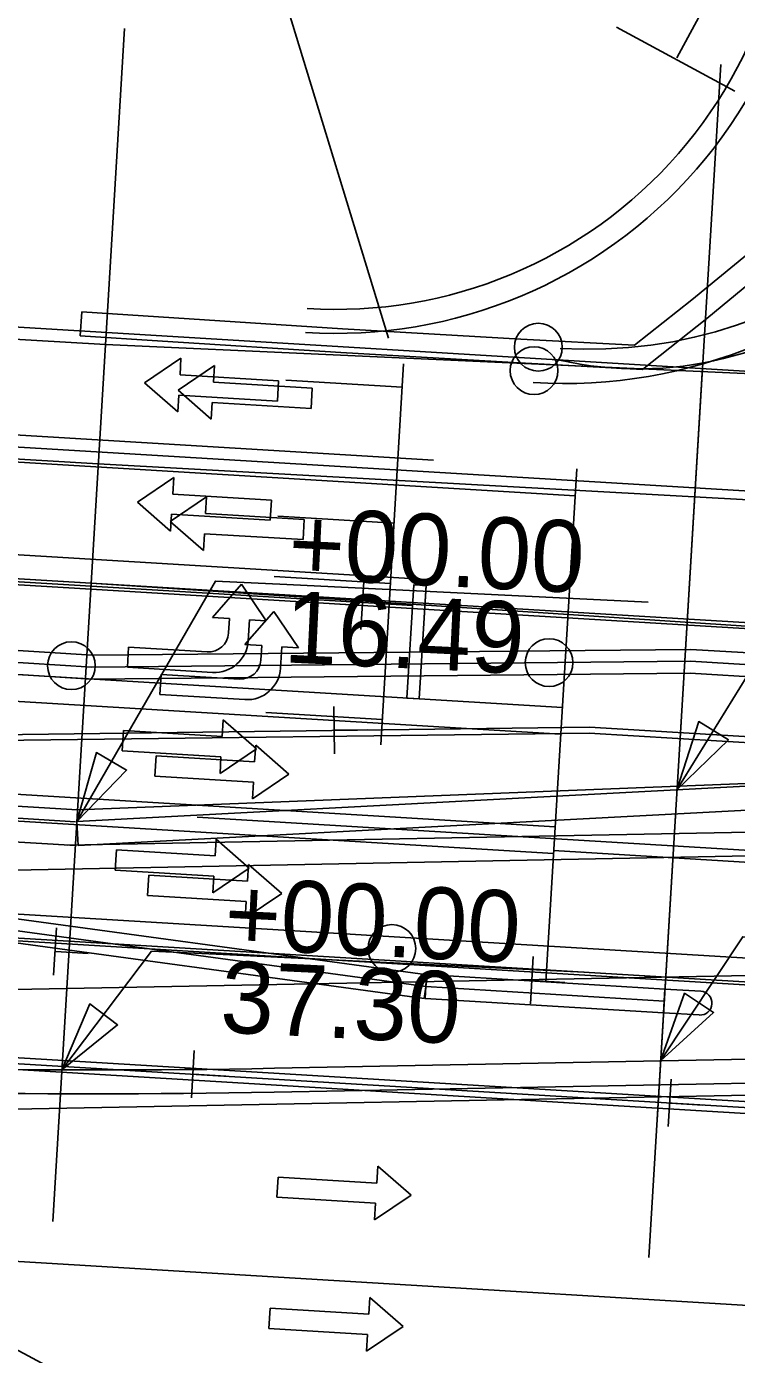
# Model space of a CAD drawing. Extents: x 659657 to 668193, y 633084 to 648639.
# Drawn here: x 662476.4 to 662535.8, y 642371.9 to 642483 of the extents above; entities that cross this region are included whole.
import ezdxf

# ---------------------------------------------------------------- set-up
doc = ezdxf.new("R2010")
doc.units = 0
for name, color, linetype in [('R_MOT_Stage 1', 7, 'Continuous'), ('R_MOT_Stage 1_Striping', 7, 'Continuous'), ('R_MOT_Stage 1A', 7, 'Continuous'), ('R_MOT_Stage 1A_Striping', 7, 'Continuous'), ('R_MOT_Stage 1B', 7, 'Continuous'), ('R_MOT_Stage 1B_Striping', 7, 'Continuous'), ('R_MOT_Stage 1C', 7, 'Continuous'), ('R_MOT_Stage 1C_Striping', 7, 'Continuous'), ('R_MOT_Stage 2', 7, 'Continuous'), ('R_MOT_Stage 2_Striping', 7, 'Continuous'), ('R_MOT_Stage 3', 7, 'Continuous'), ('R_MOT_Stage 3_Striping', 7, 'Continuous'), ('R_MOT_Stage 4', 7, 'Continuous'), ('R_MOT_STAGE 4_ALG', 7, 'Continuous'), ('R_MOT_Stage 4_Striping', 7, 'Continuous'), ('R_MOT_Stage 5', 7, 'Continuous'), ('R_MOT_Stage 5_Striping', 7, 'Continuous'), ('R_MOT_Stage 5_Striping_PPM', 7, 'Continuous'), ('R_ROW Annot', 7, 'Continuous'), ('T_SIGNAL CONTROL CABINET', 7, 'Continuous'), ('TEXT_TEMP_SIGNAL_POLES_STAGE 2', 7, 'Continuous')]:
    doc.layers.add(name, color=color, linetype=linetype)

msp = doc.modelspace()

# ---------------------------------------------------------------- linework, layer by layer
for p, q in [((662498.2, 642436.28), (662528.45, 642434.81)), ((662472.14, 642402.33), (662675.98, 642406.25)), ((662492.86, 642405.32), (662523.1, 642403.86))]:
    msp.add_line(p, q)
for points in [[(662530.86, 642419.1), (662541.99, 642437.12), (662547.99, 642436.83)], [(662480.61, 642416.45), (662492.21, 642436.57), (662498.2, 642436.28)], [(662529.49, 642396.43), (662536.36, 642406.81), (662542.36, 642406.52)], [(662479.35, 642395.67), (662486.87, 642405.62), (662492.86, 642405.32)]]:
    msp.add_lwpolyline(points)
for points in [[(662530.86, 642419.1), (662532.68, 642424.82), (662535.16, 642423.29)], [(662480.61, 642416.45), (662482.25, 642422.22), (662484.78, 642420.76)], [(662529.49, 642396.43), (662531.49, 642402.09), (662533.92, 642400.48)], [(662479.35, 642395.67), (662481.7, 642401.19), (662484.02, 642399.44)]]:
    msp.add_lwpolyline(points, close=True)
at = {"layer": 'R_MOT_Stage 1'}
for p, q in [((662478.67, 642403.6), (662478.91, 642407.57)), ((662478.84, 642405.57), (662481.55, 642405.41)), ((662518.59, 642401.19), (662518.83, 642405.16)), ((662518.77, 642403.16), (662521.48, 642403))]:
    msp.add_line(p, q, dxfattribs=at)
at = {"layer": 'R_MOT_Stage 1_Striping'}
for p, q in [((662367.61, 642453.06), (662522.33, 642443.72)), ((662367.01, 642443.08), (662508.75, 642434.52)), ((662421.3, 642429.78), (662521.12, 642423.76)), ((662365.8, 642423.12), (662520.52, 642413.78))]:
    msp.add_line(p, q, dxfattribs=at)
msp.add_lwpolyline([(662365.81, 642413.1), (662545.74, 642402.23), (662679.56, 642392.6)], dxfattribs=at)
at = {"layer": 'R_MOT_Stage 1A'}
msp.add_line((662480.9, 642457.09), (662481.03, 642459.09), dxfattribs=at)
for points in [[(662527.31, 642456.32), (662532.09, 642460.1), (662536.76, 642463.93), (662540.34, 642467.13), (662542.02, 642468.94), (662544, 642471.14), (662545.88, 642473.9), (662547.63, 642476.26), (662549.02, 642478.81), (662550.33, 642481.44), (662551.24, 642483.77), (662552.03, 642485.85), (662552.98, 642488.65), (662553.79, 642491.48), (662554.41, 642494.35), (662554.82, 642497.29), (662555.14, 642500.27), (662555.33, 642502.83), (662555.22, 642505.76), (662555.03, 642508.73), (662554.83, 642511.69), (662554.41, 642514.64), (662554.02, 642517.48)], [(662527.96, 642454.29), (662533.35, 642458.54), (662537.03, 642461.57), (662538.06, 642462.41), (662541.75, 642465.7), (662543.5, 642467.59), (662545.57, 642469.91), (662547.51, 642472.74), (662549.32, 642475.18), (662550.8, 642477.89), (662552.16, 642480.63), (662553.1, 642483.05)], [(662481.03, 642459.09), (662502.85, 642457.69), (662517.79, 642456.82), (662527.31, 642456.32)], [(662480.9, 642457.09), (662487.78, 642456.65), (662502.72, 642455.7), (662517.68, 642454.82), (662527.96, 642454.29)]]:
    msp.add_lwpolyline(points, dxfattribs=at)
at = {"layer": 'R_MOT_Stage 1A_Striping'}
for points in [[(662527.96, 642454.29), (662533.35, 642458.54), (662537.03, 642461.57), (662538.06, 642462.41), (662541.75, 642465.7), (662543.5, 642467.59), (662545.57, 642469.91), (662547.51, 642472.74), (662549.32, 642475.18), (662550.8, 642477.89), (662552.16, 642480.63), (662553.1, 642483.05)], [(662480.9, 642457.09), (662487.78, 642456.65), (662502.72, 642455.7), (662517.68, 642454.82), (662527.96, 642454.29)]]:
    msp.add_lwpolyline(points, dxfattribs=at)
at = {"layer": 'R_MOT_Stage 1B'}
msp.add_arc((662502.32, 642497.3), 38, 266.3389, 11.5452, dxfattribs=at)
at = {"layer": 'R_MOT_Stage 1B_Striping'}
msp.add_arc((662502.32, 642497.3), 40, 266.3389, 11.5452, dxfattribs=at)
at = {"layer": 'R_MOT_Stage 1C'}
msp.add_circle((662518.89, 642454.18), 2, dxfattribs=at)
at = {"layer": 'R_MOT_Stage 1C_Striping'}
msp.add_arc((662521.39, 642495.1), 42, 266.4975, 11.5452, dxfattribs=at)
at = {"layer": 'R_MOT_Stage 2'}
for p, q in [((662532.85, 642402.26), (662529.85, 642402.44)), ((662529.73, 642400.45), (662532.73, 642400.27))]:
    msp.add_line(p, q, dxfattribs=at)
for points in [[(662469.95, 642407.06), (662509.69, 642401.66), (662509.96, 642403.64), (662470.22, 642409.05)], [(662509.89, 642403.65), (662509.77, 642401.65), (662529.73, 642400.45), (662529.85, 642402.44)]]:
    msp.add_lwpolyline(points, close=True, dxfattribs=at)
for centre in [(662519.25, 642456.14), (662506.99, 642405.83)]:
    msp.add_circle(centre, 2, dxfattribs=at)
msp.add_arc((662532.79, 642401.26), 1, 266.5452, 86.5452, dxfattribs=at)
at = {"layer": 'R_MOT_Stage 2_Striping'}
for points in [[(662412.66, 642452.6), (662510.48, 642446.69)], [(662412.06, 642442.61), (662509.88, 642436.71)], [(662411.46, 642432.63), (662521.26, 642426)], [(662410.85, 642422.65), (662520.65, 642416.02)], [(662470.14, 642409.05), (662544.65, 642404.55)]]:
    msp.add_lwpolyline(points, dxfattribs=at)
msp.add_lwpolyline([(662509.28, 642426.73), (662509.87, 642436.21), (662508.84, 642436.27), (662508.25, 642426.79)], close=True, dxfattribs=at)
msp.add_arc((662527.6, 642484.6), 30.27, 257.4346, 2.4822, dxfattribs=at)
at = {"layer": 'R_MOT_Stage 3'}
for p, q in [((662301.8, 642441.26), (662481.9, 642430.38)), ((662345.58, 642436.61), (662481.85, 642428.38)), ((662481.9, 642430.38), (662532.02, 642430.86)), ((662532.02, 642430.86), (662660.67, 642423.1)), ((662481.85, 642428.38), (662531.97, 642428.86)), ((662531.97, 642428.86), (662661.25, 642421.06)), ((662497.17, 642395.81), (662624.87, 642398.26)), ((662497.13, 642393.81), (662624.91, 642396.26))]:
    msp.add_line(p, q, dxfattribs=at)
for centre in [(662520.15, 642429.75), (662480.16, 642429.49)]:
    msp.add_circle(centre, 2, dxfattribs=at)
for centre in [(662482.52, 643157.67), (662482.48, 643155.67)]:
    msp.add_arc(centre, 762, 266.54523, 271.10143, dxfattribs=at)
at = {"layer": 'R_MOT_Stage 3_Striping'}
for p, q in [((661885.4, 642492.44), (662483.02, 642456.36)), ((661899.48, 642481.57), (662482.41, 642446.38)), ((662012.67, 642464.72), (662481.81, 642436.4)), ((662483.02, 642456.36), (662582.93, 642451.83)), ((662482.41, 642446.38), (662582.26, 642440.85)), ((662481.81, 642436.4), (662581.6, 642429.87)), ((661979.29, 642409.63), (662536.82, 642375.97)), ((662471.94, 642392.32), (662695.17, 642396.61))]:
    msp.add_line(p, q, dxfattribs=at)
at = {"layer": 'R_MOT_Stage 4'}
for p, q in [((662480.49, 642416.44), (662024.68, 642443.96)), ((662480.49, 642414.44), (662024.34, 642441.98)), ((662479.84, 642414.48), (662675.81, 642418.25))]:
    msp.add_line(p, q, dxfattribs=at)
msp.add_lwpolyline([(662480.71, 642414.45), (662601.2, 642420.82), (662601.1, 642422.81), (662480.61, 642416.45)], close=True, dxfattribs=at)
at = {"layer": 'R_MOT_STAGE 4_ALG'}
msp.add_line((662472.14, 642402.33), (662675.98, 642406.25), dxfattribs=at)
at = {"layer": 'R_MOT_Stage 4_Striping'}
for p, q in [((662472.35, 642412.33), (662675.84, 642416.25)), ((661979.29, 642409.63), (662536.82, 642375.97)), ((662472.14, 642402.33), (662675.98, 642406.25)), ((662471.94, 642392.32), (662695.17, 642396.61))]:
    msp.add_line(p, q, dxfattribs=at)
at = {"layer": 'R_MOT_Stage 5'}
for p, q in [((662504.63, 642436.5), (662504.39, 642432.53)), ((662504.45, 642434.53), (662501.74, 642434.7)), ((662502.18, 642422.11), (662502.13, 642426.09)), ((662502.21, 642424.09), (662504.93, 642424.12)), ((662490.2, 642393.34), (662490.44, 642397.31)), ((662490.38, 642395.31), (662493.09, 642395.14)), ((662530.13, 642390.93), (662530.37, 642394.9)), ((662530.31, 642392.9), (662533.02, 642392.73))]:
    msp.add_line(p, q, dxfattribs=at)
at = {"layer": 'R_MOT_Stage 5_Striping'}
for p, q in [((661919.1, 642491.41), (662682.71, 642445.31)), ((661918.5, 642481.43), (662682.11, 642435.33)), ((662431.9, 642439.41), (662599.22, 642429.31)), ((662359.45, 642421.75), (662523.51, 642423.86)), ((662523.51, 642423.86), (662632.67, 642417.27)), ((662520.53, 642414.02), (662705.2, 642402.88)), ((662410.13, 642410.67), (662704.6, 642392.89)), ((662409.53, 642400.69), (662713.96, 642382.31))]:
    msp.add_line(p, q, dxfattribs=at)
at = {"layer": 'R_MOT_Stage 5_Striping_PPM'}
for radius, end in [(238.73, 86.5452), (253.73, 62.8692)]:
    msp.add_arc((662357.6, 642147.63), radius, 156.1234, end, dxfattribs=at)
at = {"layer": 'R_ROW Annot'}
for p, q in [((662506.71, 642456.91), (662489.03, 642514.72)), ((662507.97, 642454.75), (662507.04, 642439.31)), ((662507.85, 642452.8), (662498.12, 642453.38)), ((662507.17, 642441.42), (662497.43, 642442.01)), ((662506.98, 642438.32), (662506.05, 642422.88)), ((662506.86, 642436.37), (662497.13, 642436.95)), ((662506.18, 642424.99), (662496.44, 642425.58))]:
    msp.add_line(p, q, dxfattribs=at)
at = {"layer": 'T_SIGNAL CONTROL CABINET'}
for p, q in [((662478.59, 642383), (662484.61, 642482.81)), ((662534.52, 642479.8), (662528.5, 642379.98)), ((662489.33, 642455.23), (662486.28, 642453.16)), ((662489.33, 642455.23), (662489.25, 642453.83)), ((662489.09, 642452.54), (662492.14, 642454.61)), ((662489.25, 642453.83), (662497.51, 642453.33)), ((662492.06, 642453.21), (662492.14, 642454.61)), ((662532.99, 642454.45), (662529.19, 642391.46)), ((662486.28, 642453.16), (662489.06, 642450.74)), ((662492.06, 642453.21), (662500.32, 642452.71)), ((662497.51, 642453.33), (662497.4, 642451.64)), ((662500.22, 642451.02), (662500.32, 642452.71)), ((662489.14, 642452.14), (662489.06, 642450.74)), ((662491.87, 642450.12), (662489.09, 642452.54)), ((662489.14, 642452.14), (662497.4, 642451.64)), ((662491.87, 642450.12), (662491.95, 642451.52)), ((662491.95, 642451.52), (662500.22, 642451.02)), ((662488.73, 642445.25), (662485.68, 642443.18)), ((662488.73, 642445.25), (662488.64, 642443.84)), ((662488.64, 642443.84), (662496.9, 642443.35)), ((662485.68, 642443.18), (662488.46, 642440.76)), ((662488.43, 642441.56), (662491.48, 642443.63)), ((662491.39, 642442.23), (662491.48, 642443.63)), ((662496.9, 642443.35), (662496.8, 642441.66)), ((662491.21, 642439.14), (662488.43, 642441.56)), ((662488.54, 642442.16), (662488.46, 642440.76)), ((662488.54, 642442.16), (662496.8, 642441.66)), ((662491.39, 642442.23), (662499.65, 642441.73)), ((662499.55, 642440.04), (662499.65, 642441.73)), ((662491.21, 642439.14), (662491.29, 642440.54)), ((662491.29, 642440.54), (662499.55, 642440.04)), ((662431.88, 642438.91), (662599.16, 642428.81)), ((662481.88, 642429.38), (662344.64, 642437.67)), ((662345.58, 642436.61), (662481.85, 642428.38)), ((662494.4, 642436.31), (662491.98, 642433.53)), ((662496.47, 642433.26), (662494.4, 642436.31)), ((662497.11, 642434.04), (662494.69, 642431.26)), ((662499.18, 642430.99), (662497.11, 642434.04)), ((662493.38, 642433.45), (662491.98, 642433.53)), ((662493.31, 642432.23), (662493.38, 642433.45)), ((662494.96, 642431.57), (662495.06, 642433.34)), ((662496.47, 642433.26), (662495.06, 642433.34)), ((662484.94, 642431.04), (662484.84, 642429.36)), ((662491.52, 642430.65), (662484.94, 642431.04)), ((662496.09, 642431.17), (662494.69, 642431.26)), ((662496.02, 642429.96), (662496.09, 642431.17)), ((662497.67, 642429.29), (662497.78, 642431.07)), ((662499.18, 642430.99), (662497.78, 642431.07)), ((662532, 642429.86), (662481.88, 642429.38)), ((662491.98, 642428.93), (662484.84, 642429.36)), ((662852, 642410.54), (662532, 642429.86)), ((662481.85, 642428.38), (662531.97, 642428.86)), ((662487.66, 642428.77), (662487.55, 642427.09)), ((662494.23, 642428.37), (662487.66, 642428.77)), ((662531.97, 642428.86), (662721.67, 642417.41)), ((662494.69, 642426.66), (662487.55, 642427.09)), ((662492.78, 642423.56), (662492.87, 642424.96)), ((662495.65, 642422.54), (662492.87, 642424.96)), ((662523.53, 642424.36), (662359.46, 642422.25)), ((662484.42, 642422.37), (662484.52, 642424.06)), ((662492.78, 642423.56), (662484.52, 642424.06)), ((662632.7, 642417.77), (662523.53, 642424.36)), ((662495.59, 642422.84), (662495.5, 642421.44)), ((662495.59, 642422.84), (662498.37, 642420.42)), ((662492.68, 642421.87), (662484.42, 642422.37)), ((662487.24, 642421.94), (662487.14, 642420.25)), ((662495.5, 642421.44), (662487.24, 642421.94)), ((662492.6, 642420.47), (662495.65, 642422.54)), ((662492.6, 642420.47), (662492.68, 642421.87)), ((662498.37, 642420.42), (662495.32, 642418.35)), ((662495.4, 642419.76), (662487.14, 642420.25)), ((662495.4, 642419.76), (662495.32, 642418.35)), ((662580.43, 642411.41), (662490.7, 642416.83)), ((662492.18, 642413.58), (662492.27, 642414.98)), ((662495.04, 642412.56), (662492.27, 642414.98)), ((662483.82, 642412.39), (662483.92, 642414.08)), ((662492.18, 642413.58), (662483.92, 642414.08)), ((662494.99, 642412.86), (662494.9, 642411.46)), ((662494.99, 642412.86), (662497.77, 642410.44)), ((662492.08, 642411.89), (662483.82, 642412.39)), ((662486.64, 642411.96), (662486.54, 642410.27)), ((662494.9, 642411.46), (662486.64, 642411.96)), ((662491.99, 642410.49), (662495.04, 642412.56)), ((662491.99, 642410.49), (662492.08, 642411.89)), ((662497.77, 642410.44), (662494.71, 642408.37)), ((662494.8, 642409.77), (662486.54, 642410.27)), ((662494.8, 642409.77), (662494.71, 642408.37)), ((662509.83, 642402.65), (662529.79, 642401.44)), ((662409.51, 642400.19), (662713.92, 642381.81)), ((662505.81, 642387.61), (662505.72, 642386.21)), ((662505.81, 642387.61), (662508.59, 642385.19)), ((662497.46, 642386.71), (662497.36, 642385.02)), ((662505.72, 642386.21), (662497.46, 642386.71)), ((662505.62, 642384.53), (662497.36, 642385.02)), ((662508.59, 642385.19), (662505.54, 642383.12)), ((662505.62, 642384.53), (662505.54, 642383.12)), ((662505.14, 642376.63), (662505.06, 642375.23)), ((662505.14, 642376.63), (662507.92, 642374.21)), ((662496.8, 642375.73), (662496.7, 642374.04)), ((662505.06, 642375.23), (662496.8, 642375.73)), ((662504.96, 642373.55), (662496.7, 642374.04)), ((662507.92, 642374.21), (662504.87, 642372.14)), ((662504.96, 642373.55), (662504.87, 642372.14))]:
    msp.add_line(p, q, dxfattribs=at)
for points in [[(661928.71, 642451.96), (661958.63, 642448.95), (662480.67, 642417.43), (662594.08, 642421.9)], [(662522.46, 642445.97), (662519.87, 642403.04)], [(662509.88, 642436.71), (662509.55, 642431.22)], [(661935.43, 642430.18), (661955.33, 642428.17), (661975.21, 642425.91), (662254.75, 642409.03), (662547.22, 642391.38)], [(662410.19, 642411.67), (662470.08, 642408.05), (662509.83, 642402.65)]]:
    msp.add_lwpolyline(points, dxfattribs=at)
for centre, radius, start, end in [((662523.46, 642494.97), 39, 266.4975, 353.1166), ((662491.62, 642432.33), 1.69, 266.5452, 356.5452), ((662492.15, 642431.74), 2.81, 266.5452, 356.5452), ((662494.33, 642430.06), 1.69, 266.5452, 356.5452), ((662494.86, 642429.46), 2.81, 266.5452, 356.5452)]:
    msp.add_arc(centre, radius, start, end, dxfattribs=at)
at = {"layer": 'TEXT_TEMP_SIGNAL_POLES_STAGE 2'}
for p, q in [((662530.85, 642480.36), (662534.51, 642487.11)), ((662535.69, 642477.55), (662525.8, 642482.91))]:
    msp.add_line(p, q, dxfattribs=at)

# ---------------------------------------------------------------- texts
for s, p in [('+00.00', (662498.23, 642436.78)), ('16.49', (662497.89, 642429.78)), ('+00.00', (662492.88, 642405.82)), ('37.30', (662492.54, 642398.83))]:
    msp.add_text(s, height=6, rotation=357.2199).set_placement(p)

doc.saveas('drawing.dxf')
